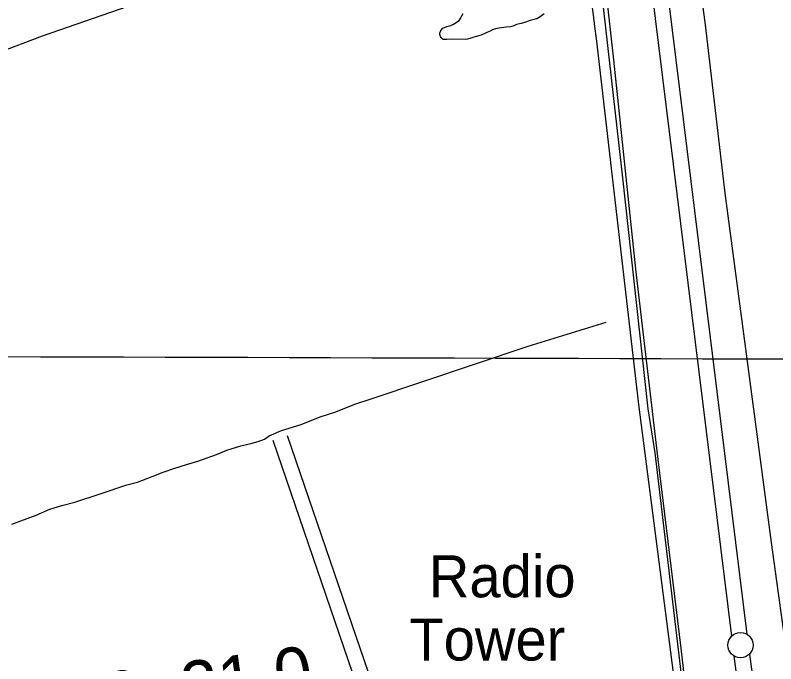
# Model space of a CAD drawing. Extents: x 3161564 to 3199464, y 849354 to 874788.
# Drawn here: x 3173329 to 3174832, y 860252 to 861534 of the extents above; entities that cross this region are included whole.
import ezdxf

# ---------------------------------------------------------------- set-up
doc = ezdxf.new("R2010")
doc.units = 0
for name, color, linetype in [('V-GRID-MAJR', 7, 'Continuous'), ('V-LEVE-TOET', 7, 'Continuous'), ('V-ROAD-CNTR', 7, 'Continuous'), ('V-SITE-VEGE', 7, 'Continuous'), ('V-SURV-IDEN', 7, 'Continuous'), ('V-SURV-LINE', 7, 'Continuous'), ('V-TOPO-SHOR', 7, 'Continuous'), ('V-TOPO-TOWR-IDEN', 7, 'Continuous')]:
    doc.layers.add(name, color=color, linetype=linetype)

msp = doc.modelspace()

# ---------------------------------------------------------------- linework, layer by layer
at = {"layer": 'V-GRID-MAJR'}
msp.add_spline([(3165780.446, 860882.501), (3171010.106, 860866.147), (3176239.768, 860850.5530000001), (3181469.433, 860835.721), (3186699.099, 860821.649), (3191928.768, 860808.338), (3197158.438, 860795.787), (3197158.4390000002, 860795.787)], degree=3, dxfattribs=at)
at = {"layer": 'V-LEVE-TOET'}
for points in [[(3174688.726000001, 859906.0229999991), (3174645.122000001, 860283.3069999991), (3174599.505000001, 860655.6009999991), (3174555.7860000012, 861025.927999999), (3174511.723000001, 861445.3609999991), (3174468.371000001, 861837.7209999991), (3174411.101000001, 862323.096999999), (3174386.255000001, 862502.898999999), (3174375.615000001, 862583.876999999), (3174373.365000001, 862634.560999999), (3174374.682000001, 862690.5959999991), (3174380.187000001, 862765.8949999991), (3174413.872000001, 863141.1209999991), (3174417.925000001, 863172.2039999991)], [(3174583.414000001, 862815.138999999), (3174578.906000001, 862776.552999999), (3174573.247000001, 862715.1739999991), (3174571.541000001, 862682.3429999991), (3174572.213000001, 862652.947999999), (3174572.305000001, 862611.964999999), (3174572.004000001, 862570.6039999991), (3174573.069000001, 862518.3919999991), (3174573.567000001, 862501.7599999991), (3174581.282000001, 862384.4879999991), (3174614.128000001, 862150.814999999), (3174645.001000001, 861868.4609999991), (3174692.089000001, 861514.7019999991), (3174731.025000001, 861182.341999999), (3174779.510000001, 860819.665999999), (3174822.782000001, 860492.260999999), (3174886.602000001, 860028.812999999)]]:
    msp.add_lwpolyline(points, dxfattribs=at)
at = {"layer": 'V-ROAD-CNTR'}
for points in [[(3174476.9130093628, 861487.6619971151), (3174560.428842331, 860764.5034434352), (3174681.731599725, 859827.2153180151)], [(3174154.239654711, 859844.739282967), (3174110.9537412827, 859877.7142170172), (3174098.239766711, 859914.250143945), (3174111.1397409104, 859976.979018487), (3174103.351756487, 860011.913948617), (3173867.150228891, 860702.987566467)], [(3174590.495782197, 858409.343153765), (3174560.547842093, 858478.5810152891), (3174533.460896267, 858560.8368507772), (3174496.6929698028, 858707.2065580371), (3174456.492050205, 858843.376285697), (3174434.6600938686, 858928.7031150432), (3174172.0396191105, 859756.3424597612), (3174151.0106611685, 859792.802386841), (3174138.393686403, 859819.0973342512), (3174085.5877920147, 859859.3242537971), (3174067.1898288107, 859912.1981480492), (3174080.459802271, 859976.7250189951), (3174074.429814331, 860003.7739648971), (3173838.7622856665, 860693.285585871)]]:
    msp.add_lwpolyline(points, dxfattribs=at)
msp.add_arc((3183283.5931913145, 864449.8128385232), 10983.59938497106, 199.75530883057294, 205.76161160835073, dxfattribs=at)
for points in [[(3174388.5601860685, 862254.354463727), (3174430.0761030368, 861863.143246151), (3174476.9130093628, 861487.6619971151)], [(3172633.7876956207, 861383.7532049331), (3172802.5873580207, 860880.4682115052), (3172972.2250187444, 860440.5450913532), (3173132.309698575, 860039.2768938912), (3173355.914251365, 859565.2138420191), (3173614.6467338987, 859060.7818508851), (3173833.7812956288, 858663.2596459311)]]:
    msp.add_spline(points, degree=3, dxfattribs=at)
at = {"layer": 'V-SITE-VEGE'}
msp.add_lwpolyline([(3174374.423000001, 861535.988999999), (3174366.539000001, 861530.1869999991), (3174359.430000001, 861526.594999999), (3174346.761000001, 861523.096999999), (3174335.565000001, 861518.8309999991), (3174328.860000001, 861517.087999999), (3174319.551000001, 861515.0179999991), (3174314.323000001, 861512.876999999), (3174307.612000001, 861510.765999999), (3174299.065000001, 861509.792999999), (3174280.846000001, 861507.128999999), (3174273.764000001, 861505.020999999), (3174267.4110000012, 861502.1599999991), (3174261.065000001, 861499.6699999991), (3174249.477000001, 861494.297999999), (3174237.556000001, 861491.157999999), (3174233.445000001, 861489.371999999), (3174227.1070000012, 861487.2529999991), (3174222.638000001, 861486.211999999), (3174218.175000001, 861485.5469999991), (3174192.5900000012, 861485.9709999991), (3174182.194000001, 861485.400999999), (3174177.004000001, 861485.486999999), (3174174.416000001, 861485.9029999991), (3174170.762000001, 861489.302999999), (3174169.687000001, 861491.542999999), (3174168.272000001, 861495.6479999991), (3174167.944000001, 861498.2509999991), (3174169.884000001, 861503.408999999), (3174174.043000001, 861508.162999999), (3174181.885000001, 861511.3699999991), (3174190.081000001, 861513.4609999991), (3174195.307000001, 861515.596999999), (3174206.191000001, 861523.204999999), (3174208.466000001, 861526.135999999), (3174214.208000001, 861536.797999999)], dxfattribs=at)
at = {"layer": 'V-SURV-LINE'}
for points in [[(3174744.864824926, 860307.1718463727), (3174478.717727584, 862459.9290544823)], [(3174508.4891627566, 862463.6252532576), (3174774.6362102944, 860310.8684479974)], [(3174800.2899450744, 859892.1816902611), (3174749.99136915, 860267.3822938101)], [(3174779.7260035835, 860271.3636927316), (3174830.024544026, 859896.1633538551)]]:
    msp.add_lwpolyline(points, dxfattribs=at)
msp.add_circle((3174762.20297, 860289.1830599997), 25, dxfattribs=at)
at = {"layer": 'V-TOPO-SHOR'}
for points in [[(3174380.085504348, 862813.0626956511), (3174367.6509478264, 862653.1898260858), (3174372.9800434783, 862566.1479304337), (3174388.967330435, 862395.616869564), (3174403.178252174, 862297.9167826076), (3174438.705556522, 861983.5001391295), (3174465.3510347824, 861747.2435652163), (3174476.009226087, 861683.2944173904), (3174483.114686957, 861640.661652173), (3174488.443782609, 861573.1597739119), (3174529.300182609, 861212.5576347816), (3174579.038408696, 860756.031773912), (3174593.249330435, 860668.98987826), (3174646.540286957, 860219.5694782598)], [(3174406.049000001, 861871.3629999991), (3174192.168000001, 861792.9169999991), (3174158.343000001, 861782.3389999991), (3174134.330000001, 861772.0419999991), (3174108.331000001, 861762.890999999), (3174079.854000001, 861752.2229999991), (3174039.193000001, 861732.3999999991), (3173960.973000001, 861705.177999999), (3173765.453000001, 861631.996999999), (3173584.020000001, 861561.9269999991), (3173381.871000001, 861492.1989999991), (3173201.358000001, 861423.670999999), (3173075.946000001, 861372.498999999), (3172901.420000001, 861302.3119999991), (3172810.055000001, 861261.716999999), (3172801.883000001, 861258.9949999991)], [(3174032.328000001, 860775.9539999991), (3174342.827000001, 860880.0129999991), (3174496.699000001, 860927.0389999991)], [(3173322.5190000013, 860528.3809999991), (3173370.045000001, 860545.6399999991), (3173397.654000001, 860557.658999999), (3173421.170000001, 860564.8459999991), (3173446.688000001, 860571.773999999), (3173497.091000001, 860587.871999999), (3173549.528000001, 860605.7179999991), (3173570.788000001, 860611.1569999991), (3173599.714000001, 860622.0399999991), (3173621.251000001, 860630.817999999), (3173644.563000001, 860639.1209999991), (3173667.188000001, 860646.3209999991), (3173689.580000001, 860652.856999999), (3173726.565000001, 860666.057999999), (3173747.426000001, 860674.4019999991), (3173774.7490000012, 860682.636999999), (3173794.440000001, 860687.657999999), (3173808.991000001, 860691.6499999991), (3173821.771000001, 860696.339999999), (3173830.563000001, 860702.432999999), (3173855.251000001, 860713.1619999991), (3173893.998000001, 860724.996999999), (3173931.462000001, 860740.1959999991), (3173962.599000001, 860750.150999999), (3174000.289000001, 860765.344999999), (3174032.328000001, 860775.9539999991)]]:
    msp.add_lwpolyline(points, dxfattribs=at)

# ---------------------------------------------------------------- texts
at = {"layer": 'V-SURV-IDEN'}
msp.add_text('700+21.0', height=100, rotation=7.804444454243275, dxfattribs=at).set_placement((3173365.3139992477, 860113.9300174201))
at = {"layer": 'V-TOPO-TOWR-IDEN'}
for s, p in [('Radio', (3174146.3368844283, 860383.7012291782)), (' Tower', (3174076.961760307, 860258.8317425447))]:
    msp.add_text(s, height=82.999832, dxfattribs=at).set_placement(p)

doc.saveas('drawing.dxf')
